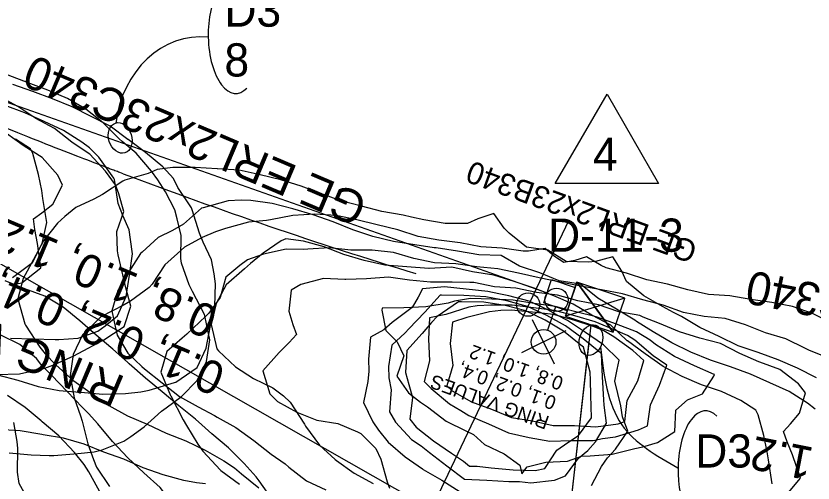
# Model space of a CAD drawing. Extents: x 1638506 to 1658005, y 834807 to 846788.
# Drawn here: x 1640119.8 to 1640408.1, y 842707.5 to 842876.3 of the extents above; entities that cross this region are included whole.
import ezdxf

# ---------------------------------------------------------------- set-up
doc = ezdxf.new("R2010")
doc.units = 0
for name, color, linetype in [('Default', 7, 'Continuous'), ('Old_Level_1', 7, 'Continuous'), ('Old_Level_2', 7, 'Continuous'), ('Scratch_Level_0', 7, 'Continuous')]:
    doc.layers.add(name, color=color, linetype=linetype)

msp = doc.modelspace()

# ---------------------------------------------------------------- linework, layer by layer
at = {"layer": 'Default'}
for p, q in [((1640075.68, 842859.56), (1640311.9, 842776.31)), ((1640114.23, 842786.79), (1640314.63, 842672.83)), ((1640335.82, 842762.04), (1640322.64, 842780.16)), ((1640339.96, 842774.32), (1640318.49, 842767.88)), ((1640314.9, 842771.23), (1640312.04, 842762.75)), ((1640314.6, 842750.52), (1640306.64, 842766.54)), ((1640303.08, 842545.23), (1640327.81, 842764.74)), ((1640318.6, 842762.5), (1640302.6, 842754.57)), ((1640314.65, 842760.54), (1640314.65, 842760.54)), ((1640303.88, 842552.36), (1640327.15, 842758.82)), ((1640310.61, 842758.51), (1640310.61, 842758.51))]:
    msp.add_line(p, q, dxfattribs=at)
for points in [[(1640352.23, 842815.78), (1640314.84, 842815.78), (1640333.66, 842848.05)], [(1640321.99, 842778.25), (1640319.14, 842769.8), (1640310.66, 842772.66), (1640313.51, 842781.11)], [(1640339.96, 842774.32), (1640322.64, 842780.16), (1640318.49, 842767.88), (1640335.82, 842762.04)], [(1640329.23, 842771.1), (1640318.49, 842767.88), (1640322.64, 842780.16)], [(1640329.23, 842771.1), (1640335.82, 842762.04), (1640339.96, 842774.32)]]:
    msp.add_lwpolyline(points, close=True, dxfattribs=at)
msp.add_circle((1640310.61, 842758.55), 4.47, dxfattribs=at)
for centre, major_axis, ratio, start_param, end_param in [((1640198.9, 842868.83), (-0.49, 20.52), 0.466223, 5.884886, 7.853982), ((1640185.55, 842834.26), (-3.78, -34.34), 0.862742, 3.141593, 4.712389), ((1640198.9, 842868.83), (-0.49, 20.52), 0.466223, 1.570796, 3.572354), ((1640368.8, 842713.14), (-0.49, -20.52), 0.466223, 2.710831, 4.712389), ((1640368.8, 842713.14), (-0.49, -20.52), 0.466223, 4.712389, 6.681485)]:
    msp.add_ellipse(centre, major_axis=major_axis, ratio=ratio, start_param=start_param, end_param=end_param, dxfattribs=at)
for centre, major_axis in [((1640157.49, 842832.23), (1.72, -5.4)), ((1640327.74, 842759.18), (1.72, 5.4))]:
    msp.add_ellipse(centre, major_axis=major_axis, ratio=0.730797, dxfattribs=at)
msp.add_spline([(1640331.21, 842756.76), (1640338.9, 842728.6), (1640359.22, 842712.98)], degree=3, dxfattribs=at)
at = {"layer": 'Old_Level_1'}
for points in [[(1640113.03, 842746.65), (1640120.46, 842744.71), (1640127.77, 842742.43), (1640135.38, 842740.98), (1640142.84, 842740.36), (1640143.29, 842740.34), (1640151.19, 842739.68), (1640159.42, 842739.92), (1640164.95, 842740.45), (1640168, 842741.12), (1640177.13, 842743.83), (1640177.61, 842743.99), (1640185.3, 842749.33), (1640188.61, 842756.26), (1640190.07, 842763.87), (1640191.69, 842771.42), (1640191.96, 842779.47), (1640191.42, 842783.1), (1640190.48, 842788.15), (1640187.45, 842794.55), (1640186.15, 842797.87), (1640183.57, 842806.27), (1640183.31, 842807.04), (1640178.34, 842814.27), (1640176.76, 842817.56), (1640172.93, 842821.76), (1640166.66, 842826.92), (1640160.32, 842831.69), (1640160.27, 842831.72), (1640153.85, 842836.44), (1640146.99, 842839.96), (1640140.11, 842843.44), (1640133.04, 842846.37), (1640125.87, 842849.03), (1640118.63, 842851.51)], [(1640117.85, 842759.92), (1640125.88, 842759.6), (1640133.96, 842759.43), (1640135.26, 842759.4), (1640142.27, 842759.89), (1640149.36, 842762.41), (1640152.03, 842764.34), (1640156.55, 842767.93), (1640159.61, 842774.96), (1640160.88, 842782.64), (1640161.88, 842790.41), (1640161.8, 842791.19), (1640160.72, 842798.98), (1640158.4, 842804.22), (1640156.8, 842808.55), (1640155.47, 842817.17), (1640155.16, 842817.67), (1640149.81, 842825.34), (1640146.39, 842828.62), (1640143.62, 842830.7), (1640137.02, 842834.93), (1640130.05, 842838.15), (1640123.05, 842841.29), (1640115.86, 842843.92)], [(1640118.59, 842781.75), (1640125.83, 842787.25), (1640129.31, 842794.13), (1640130.93, 842801.68), (1640129.51, 842810.34), (1640129.12, 842813.24), (1640127.94, 842819.05), (1640125.84, 842826.6), (1640125.02, 842828.25), (1640119.57, 842831.74)], [(1640409.37, 842745.59), (1640402.5, 842749.07), (1640395.43, 842752.01), (1640388.25, 842754.66), (1640381.01, 842757.14), (1640374.11, 842760.54), (1640367.15, 842763.77), (1640360.44, 842767.71), (1640357.63, 842769.15), (1640353.6, 842771.29), (1640346.89, 842775.21), (1640340.61, 842780.32), (1640338.91, 842784.1), (1640335.71, 842789.23), (1640329.43, 842787.55), (1640326.88, 842787.35), (1640318.81, 842787.53), (1640312.2, 842791.73), (1640304.43, 842792.76), (1640298.13, 842797.82), (1640296.31, 842799.61), (1640292.57, 842804.93), (1640286.83, 842803.06), (1640283.1, 842801.26), (1640275, 842801.37), (1640267.34, 842802.69), (1640262.87, 842803.64), (1640259.8, 842804.34), (1640252.13, 842805.63), (1640244.72, 842807.64), (1640237.24, 842809.47), (1640230.1, 842812.22), (1640222.9, 842814.8), (1640215.6, 842817.1), (1640208.09, 842818.85), (1640200.57, 842820.56), (1640192.62, 842821.08), (1640192.56, 842821.09), (1640184.64, 842821.51), (1640176.52, 842821.58), (1640170.89, 842820.83), (1640167.56, 842819.33), (1640159.11, 842816.98), (1640158.41, 842816.56), (1640151.04, 842811.78), (1640147.91, 842810.07), (1640141.47, 842807.12), (1640137.51, 842803.85), (1640134.76, 842801.42), (1640129.79, 842795.09), (1640126.18, 842788.26), (1640122.41, 842781.49), (1640120.48, 842774.05), (1640122.94, 842765.02)], [(1640408.78, 842734.25), (1640406.01, 842736.34), (1640399.4, 842740.57), (1640392.44, 842743.79), (1640385.44, 842746.92), (1640378.25, 842749.55), (1640370.96, 842751.89), (1640363.88, 842754.79), (1640356.99, 842758.23), (1640350.28, 842762.18), (1640344.24, 842765.88), (1640343.66, 842766.35), (1640337, 842770.42), (1640330.27, 842774.3), (1640323.97, 842779.34), (1640316.3, 842780.63), (1640309.21, 842783.53), (1640301.92, 842785.87), (1640295.21, 842789.8), (1640287.14, 842790), (1640279.49, 842791.35), (1640271.77, 842792.51), (1640271.03, 842792.53), (1640264.02, 842793.58), (1640256.35, 842794.86), (1640248.86, 842796.66), (1640241.57, 842798.98), (1640234.48, 842801.88), (1640227.29, 842804.48), (1640219.91, 842806.58), (1640212.5, 842808.6), (1640204.72, 842809.6), (1640201.25, 842809.78), (1640196.53, 842809.47), (1640187.51, 842807.03), (1640186.95, 842806.85), (1640180.38, 842801.1), (1640176.37, 842798.81), (1640171.23, 842796.29), (1640165.4, 842791.02), (1640164.83, 842790.47), (1640160.61, 842783.87), (1640156.64, 842777.17), (1640154.47, 842769.82)], [(1640393.32, 842707.31), (1640391.9, 842715.97), (1640391.51, 842718.87), (1640390.32, 842724.68), (1640388.23, 842732.23), (1640387.41, 842733.89), (1640381.96, 842737.38), (1640374.99, 842740.58), (1640367.75, 842743.07), (1640360.71, 842746.09), (1640353.88, 842749.69), (1640347.39, 842754.24), (1640340.95, 842758.89), (1640340.84, 842758.98), (1640334.88, 842764.58), (1640328.03, 842768.14), (1640321.35, 842772.14), (1640314.3, 842775.15), (1640307.17, 842777.92), (1640299.92, 842780.38), (1640292.59, 842782.61), (1640284.9, 842783.84), (1640277.37, 842785.51), (1640269.2, 842785.05), (1640269.06, 842785.06), (1640261.13, 842785.63), (1640253.24, 842786.32), (1640245.69, 842787.95), (1640238.35, 842790.16), (1640231.21, 842792.91), (1640223.81, 842794.94), (1640217.4, 842795.77), (1640215.7, 842795.02), (1640209.25, 842790.59), (1640204.6, 842786.9), (1640202.44, 842784.93), (1640195.78, 842779.21), (1640192.17, 842772.38), (1640190.42, 842764.88), (1640192.43, 842756.01)], [(1640327.93, 842706.69), (1640331.59, 842713.5), (1640333.7, 842716.62), (1640336.59, 842719.82), (1640341.1, 842726.32), (1640339.11, 842731.48), (1640338.54, 842735.39), (1640336.43, 842744.3), (1640337.2, 842748.6), (1640337.93, 842751.9), (1640332.31, 842757.52), (1640325.75, 842761.88), (1640319.22, 842766.3), (1640315.58, 842768.17), (1640312.41, 842769.96), (1640305.45, 842773.21), (1640298.03, 842775.19), (1640294.46, 842775.86), (1640290.47, 842776.77), (1640282.62, 842777.58), (1640274.8, 842778.45), (1640266.87, 842777.76), (1640265.31, 842774.76), (1640263.14, 842770.98), (1640255.79, 842765.51), (1640252.85, 842762.88), (1640248.01, 842760.2), (1640247.28, 842752.32)], [(1640254.54, 842749.68), (1640254.67, 842745.52), (1640255.45, 842741.21), (1640254.86, 842733.28), (1640257, 842729.55), (1640262.85, 842723.27), (1640266.31, 842720.97), (1640269.3, 842718.62), (1640275.67, 842713.75), (1640282.04, 842708.89), (1640290.05, 842708.52), (1640298.06, 842708.15), (1640301.86, 842708.04), (1640305.99, 842707.57), (1640314.51, 842708.62), (1640318.54, 842710.1), (1640323.18, 842716.56), (1640326.56, 842719.35), (1640329.33, 842722.46), (1640333.4, 842729.12), (1640332.5, 842735.68), (1640332.45, 842737.61), (1640331.89, 842745.95), (1640331.55, 842754.22), (1640331.22, 842754.54), (1640324.93, 842759.61), (1640318.51, 842764.34), (1640311.73, 842768.1), (1640304.75, 842771.28), (1640297.36, 842773.33), (1640289.75, 842774.8), (1640281.8, 842775.31), (1640273.71, 842775.47), (1640273.26, 842775.43), (1640267.68, 842769.32), (1640261.88, 842763.29), (1640260.61, 842761.85), (1640255.71, 842757.4), (1640254.54, 842749.68)], [(1640260.65, 842747.46), (1640261.93, 842743.11), (1640263.17, 842738.4), (1640262.28, 842730.58), (1640264.48, 842727.74), (1640270.83, 842722.81), (1640277.34, 842718.32), (1640281.61, 842715.41), (1640283.76, 842713.61), (1640286.56, 842713.61), (1640291.71, 842713.09), (1640299.58, 842712.35), (1640307.61, 842712.04), (1640311.12, 842712.81), (1640315.46, 842719.37), (1640319.44, 842722.17), (1640323.22, 842724.68), (1640327.95, 842731.11), (1640327.69, 842739.34), (1640327.63, 842744.66), (1640327.43, 842747.58), (1640325.02, 842756.59), (1640324.1, 842757.34), (1640317.79, 842762.37), (1640311.13, 842766.44), (1640304.21, 842769.78), (1640296.75, 842771.67), (1640289.04, 842772.84), (1640280.97, 842773.04), (1640279.79, 842773.06), (1640272.14, 842767.7), (1640270.12, 842765.6), (1640266.65, 842761.56), (1640261.16, 842755.41), (1640260.65, 842747.46)], [(1640154.47, 842769.82), (1640155.62, 842764.16), (1640156.43, 842760.97), (1640160.24, 842754.48), (1640165.29, 842749.6), (1640166.31, 842748.79), (1640172.61, 842743.73), (1640178.96, 842738.81), (1640185.73, 842735.05), (1640191.55, 842731.9), (1640192.53, 842731.35), (1640199.31, 842727.63), (1640205.76, 842722.97), (1640212.1, 842718.03), (1640217.11, 842714.46), (1640218.53, 842713.32), (1640224.85, 842708.32), (1640231.8, 842705.06)], [(1640122.94, 842765.02), (1640123.22, 842764.59), (1640128.46, 842756.64), (1640130.37, 842754.17), (1640134.26, 842750.21), (1640140.41, 842744.74), (1640146.89, 842740.16), (1640147.25, 842739.89), (1640153.36, 842735.57), (1640160.12, 842731.79), (1640167.19, 842728.84), (1640174.13, 842725.54), (1640181.25, 842722.73), (1640188.17, 842719.37), (1640194.94, 842715.61), (1640198.78, 842712.99), (1640201.34, 842710.84), (1640207.64, 842705.78)], [(1640192.43, 842756.01), (1640193.09, 842755.27), (1640199.14, 842749.52), (1640205.74, 842745.28), (1640212.67, 842741.96), (1640216.54, 842739.09), (1640218.94, 842736.81), (1640224.15, 842728.77), (1640224.45, 842728.07), (1640229.56, 842721.28), (1640235.18, 842716.02), (1640235.66, 842715.67), (1640242.12, 842711.05), (1640248.95, 842707.43)], [(1640247.28, 842752.32), (1640247.44, 842748.02), (1640247.05, 842744.27), (1640245.48, 842736.7), (1640248.9, 842729.66), (1640250.88, 842726.59), (1640254.38, 842722.36), (1640260.56, 842716.97), (1640266.78, 842712.66), (1640267.07, 842712.48), (1640273.79, 842708.59), (1640280.4, 842704.37)], [(1640150.91, 842702.81), (1640150.68, 842703.26), (1640146.14, 842711.64), (1640144.46, 842714.27), (1640140.93, 842718.55), (1640135.28, 842724.54), (1640129.23, 842729.66), (1640128.89, 842729.97), (1640123.18, 842734.8), (1640116.77, 842739.16)], [(1640188.39, 842707.26), (1640185.06, 842707.56), (1640180.49, 842708.42), (1640173.04, 842710.55), (1640165.78, 842713.06), (1640158.76, 842716.11), (1640151.52, 842718.68), (1640144.43, 842721.6), (1640136.98, 842723.71), (1640129.61, 842724.97), (1640129.16, 842725.04), (1640121.34, 842726.38), (1640113.12, 842726.85)]]:
    msp.add_lwpolyline(points, dxfattribs=at)
msp.add_circle((1640305.02, 842772.01), 4.21, dxfattribs=at)
at = {"layer": 'Old_Level_2'}
msp.add_line((1640319.78, 842802.51), (1640164.82, 842477.58), dxfattribs=at)
msp.add_arc((1640787.74, 844492.39), 1787.5, 249.39267, 252.97707, dxfattribs=at)
msp.add_open_spline([(1640158.61, 842819.26), (1640157.59, 842819.64), (1640156.58, 842820.02), (1640154.56, 842820.79), (1640153.54, 842821.17), (1640150.51, 842822.33), (1640144.44, 842824.64), (1640130.31, 842830.13), (1640118.24, 842834.94), (1640094.16, 842844.7), (1640078.16, 842851.39), (1640030.3, 842871.79), (1639998.56, 842885.87), (1639966.8, 842899.95)], degree=3, dxfattribs=at)
at = {"layer": 'Scratch_Level_0'}
for points in [[(1640117.31, 842718.45), (1640125.31, 842717.74), (1640131.79, 842717.47), (1640133.54, 842717.55), (1640142.11, 842718.16), (1640148.09, 842718.87), (1640151, 842719.53), (1640158.77, 842722.65), (1640161.33, 842724.3), (1640166.16, 842727.83), (1640172.46, 842733.46), (1640174.06, 842734.71), (1640179.6, 842738.75), (1640185.37, 842744.61), (1640188.71, 842751.5), (1640189.95, 842759.28), (1640188.13, 842767.9), (1640188.03, 842768.41), (1640183.6, 842776.79), (1640182.41, 842779.1), (1640179.62, 842787.02), (1640179.38, 842788.7), (1640179.55, 842796.93), (1640178.08, 842802.96), (1640177.23, 842806.22), (1640173.93, 842812.78), (1640171.16, 842817.11), (1640168.77, 842820.2), (1640163.22, 842826.72), (1640158.23, 842830.9), (1640157.13, 842831.94), (1640151.28, 842837.75), (1640145.06, 842842.67), (1640138.39, 842846.54), (1640131.35, 842849.53), (1640124.15, 842852.15), (1640117.01, 842854.91)], [(1640112.67, 842746.71), (1640121.05, 842746.96), (1640121.09, 842746.96), (1640130.28, 842749.05), (1640133.18, 842750.12), (1640140.43, 842753.38), (1640142.55, 842754.46), (1640151.14, 842759.04), (1640151.22, 842759.09), (1640158.88, 842764.15), (1640161.31, 842771.43), (1640159.42, 842778.57), (1640158.93, 842780.75), (1640156.78, 842789.97), (1640156.57, 842791.43), (1640156.3, 842798.48), (1640158.85, 842805.71), (1640157, 842812.05), (1640155.85, 842815.29), (1640152.17, 842820.26), (1640146.46, 842826.39), (1640141.19, 842829.82), (1640139.99, 842830.72), (1640133.76, 842835.62), (1640126.98, 842839.23), (1640120.51, 842843.56), (1640113.75, 842847.22)], [(1640118.1, 842779.11), (1640121.87, 842779.85), (1640128.73, 842785.25), (1640127.55, 842794.06), (1640126.58, 842799.11), (1640126.09, 842802.98), (1640129.16, 842805.18), (1640133.08, 842808.33), (1640136.65, 842815.13), (1640134.92, 842818.77), (1640129.32, 842825.16), (1640122.75, 842829.26), (1640122.45, 842829.46), (1640116.38, 842833.82)], [(1640415.01, 842765.3), (1640407.92, 842768.85), (1640400.6, 842771.29), (1640393.1, 842772.79), (1640385.52, 842773.89), (1640377.97, 842775.14), (1640370.27, 842775.66), (1640362.81, 842777.37), (1640355.42, 842779.4), (1640347.93, 842780.98), (1640340.61, 842783.42), (1640333.19, 842785.29), (1640331.39, 842786.11), (1640326.17, 842789.24), (1640321.94, 842787.99), (1640317.98, 842787.27), (1640314.61, 842789.45), (1640311.17, 842792.23), (1640305.15, 842791.34), (1640303.18, 842791.27), (1640295.6, 842792.39), (1640287.91, 842792.94), (1640280.39, 842794.36), (1640272.78, 842795.31), (1640265.24, 842796.6), (1640257.93, 842799.07), (1640250.48, 842800.81), (1640243.05, 842802.7), (1640235.55, 842804.19), (1640227.86, 842804.74), (1640219.94, 842804.18), (1640211.84, 842802.66), (1640210.35, 842802.43), (1640203.87, 842801.78), (1640195.61, 842799.52), (1640191.9, 842798.31), (1640187.17, 842796.29), (1640180.75, 842792.73), (1640178.22, 842790.5), (1640173.6, 842786.35), (1640169.11, 842779.45), (1640167.96, 842778.2), (1640161.21, 842773.22), (1640158.92, 842771.98), (1640150.54, 842767.55), (1640150.17, 842767.18), (1640143.82, 842761.09), (1640140.46, 842753.96), (1640139.35, 842746.38), (1640140.81, 842738.28)], [(1640412.6, 842753.2), (1640406.74, 842755.49), (1640405.38, 842756.13), (1640398.28, 842759.66), (1640390.91, 842761.81), (1640383.69, 842764.74), (1640376.34, 842766.96), (1640368.69, 842767.72), (1640361.18, 842769.2), (1640353.9, 842771.78), (1640346.49, 842773.74), (1640339.13, 842775.96), (1640331.6, 842777.34), (1640324.06, 842778.63), (1640316.55, 842780.07), (1640309.06, 842781.63), (1640301.59, 842783.32), (1640294.11, 842784.93), (1640286.47, 842785.7), (1640278.87, 842786.73), (1640271.15, 842787.15), (1640263.65, 842788.65), (1640256.3, 842790.88), (1640248.65, 842791.65), (1640240.86, 842791.72), (1640233.23, 842792.56), (1640225.32, 842792.01), (1640223.82, 842791.94), (1640217.53, 842792.08), (1640209.36, 842790.22), (1640203.53, 842788.19), (1640200.75, 842786.15), (1640195.65, 842781.96), (1640193.7, 842774.55), (1640189.51, 842768.87), (1640188.51, 842767.78), (1640181.54, 842761.37), (1640179.91, 842759.85), (1640174.32, 842755.01), (1640172.24, 842747.62), (1640175.72, 842739.13)], [(1640212.68, 842701.37), (1640207.69, 842708.36), (1640206.63, 842709.76), (1640202.3, 842714.58), (1640196.65, 842720.3), (1640190.62, 842725.28), (1640187.04, 842728.56), (1640184.78, 842730.64), (1640178.64, 842735.43), (1640172.64, 842740.46), (1640166.63, 842745.49), (1640160.69, 842750.65), (1640160.07, 842751.19), (1640154.79, 842755.88), (1640148.81, 842760.97), (1640142.85, 842766.1), (1640136.81, 842771.06), (1640130.25, 842775.02), (1640123, 842777.66), (1640115.89, 842780.57)], [(1640397.96, 842702.63), (1640403.58, 842709.31), (1640400.64, 842717.7), (1640398.67, 842722.45), (1640397.4, 842726.15), (1640399.96, 842728.92), (1640403.15, 842732.8), (1640405.28, 842740.18), (1640402.84, 842743.39), (1640396.06, 842748.52), (1640388.8, 842751.2), (1640388.46, 842751.33), (1640381.63, 842754.37), (1640374.55, 842757.99), (1640367.12, 842759.87), (1640359.77, 842762.13), (1640352.58, 842765.18), (1640346.62, 842767.47), (1640345.36, 842768.08), (1640337.83, 842769.43), (1640330.53, 842771.96), (1640323.02, 842773.41), (1640315.62, 842775.44), (1640308.01, 842776.4), (1640300.52, 842777.94), (1640292.81, 842778.4), (1640285.34, 842780.05), (1640283.93, 842779.96), (1640277.56, 842780.13), (1640269.74, 842780.07), (1640262.09, 842780.8), (1640254.51, 842781.91), (1640246.58, 842781.29), (1640239.11, 842781.1), (1640238.75, 842781.1), (1640231.01, 842781.41), (1640222.78, 842779.28), (1640219.3, 842777.24), (1640218.44, 842769.62), (1640219.9, 842764.81), (1640221.2, 842761.27), (1640218.61, 842758.34), (1640214.97, 842754.71), (1640209.03, 842748.09), (1640211.66, 842739.76)], [(1640252.18, 842770.69), (1640252.14, 842770.03), (1640253.5, 842762.63), (1640257.65, 842758.55), (1640260.11, 842753.51), (1640257.59, 842746.21), (1640261.77, 842740.08), (1640266.07, 842736.72), (1640268.57, 842735.02), (1640275.35, 842729.95), (1640282.44, 842726.38), (1640285.25, 842725.1), (1640289.26, 842721.44), (1640296.4, 842718.12), (1640302.01, 842713.96), (1640302.74, 842710.82), (1640304.62, 842713.44), (1640311.4, 842715.13), (1640319.27, 842715.46), (1640324.37, 842717.3), (1640327.46, 842717.4), (1640335.37, 842717.99), (1640343.59, 842720.07), (1640346.55, 842720.68), (1640351.8, 842722.14), (1640358.02, 842726.2), (1640358.49, 842733.9), (1640362.69, 842737.62), (1640368.08, 842739.79), (1640372.18, 842746.11), (1640372.39, 842746.73), (1640372.32, 842746.78), (1640365.14, 842749.91), (1640358.01, 842753.27), (1640351.07, 842757.6), (1640349.17, 842759.16), (1640344.19, 842762.21), (1640336.94, 842764.97), (1640329.66, 842767.58), (1640322.23, 842769.46), (1640314.8, 842771.32), (1640307.23, 842772.45), (1640299.65, 842773.57), (1640291.92, 842773.94), (1640284.17, 842774.17), (1640278.4, 842773.27), (1640276.05, 842772.55), (1640267.98, 842771.21), (1640260.1, 842770.85), (1640252.28, 842770.71), (1640252.18, 842770.69)], [(1640267.44, 842744.25), (1640269.9, 842741.72), (1640276.6, 842736.19), (1640280.67, 842733.81), (1640283.55, 842731.91), (1640290.74, 842728.88), (1640297.91, 842725.71), (1640305.38, 842724.03), (1640312.92, 842722.72), (1640320.75, 842722.89), (1640328.56, 842722.94), (1640331.94, 842723.59), (1640336.62, 842724.23), (1640344.93, 842726.77), (1640348.17, 842728.16), (1640349.25, 842735.74), (1640352.57, 842742.88), (1640355.24, 842750.15), (1640350.24, 842753.46), (1640343.57, 842759.11), (1640340.95, 842760.8), (1640336.51, 842762.81), (1640329.3, 842765.81), (1640321.92, 842767.9), (1640314.51, 842769.85), (1640306.92, 842770.89), (1640299.29, 842771.79), (1640291.49, 842771.78), (1640286.62, 842771.63), (1640283.55, 842771.07), (1640275.22, 842768.41), (1640269.34, 842767.27), (1640269.02, 842759.53), (1640269.35, 842751.67), (1640267.44, 842744.25)], [(1640275.63, 842742.62), (1640277.53, 842740.87), (1640284.53, 842736.85), (1640291.82, 842734.26), (1640299.02, 842731.28), (1640306.56, 842729.97), (1640314.03, 842728.29), (1640321.82, 842728.28), (1640329.54, 842727.88), (1640337.55, 842728.91), (1640339.97, 842729.79), (1640340.81, 842737.42), (1640344.72, 842744.45), (1640346.88, 842751.82), (1640342.83, 842755.41), (1640336.03, 842760.41), (1640332.37, 842762.51), (1640328.95, 842764.03), (1640321.61, 842766.35), (1640314.22, 842768.38), (1640306.61, 842769.34), (1640298.94, 842770.02), (1640295.2, 842769.92), (1640291.01, 842769.38), (1640282.81, 842767.37), (1640277.7, 842765.61), (1640276.87, 842757.97), (1640277.78, 842749.99), (1640275.63, 842742.62)], [(1640186.93, 842668.27), (1640186.91, 842668.37), (1640184.98, 842677.91), (1640184.46, 842680.23), (1640182.35, 842687.89), (1640181.33, 842690.81), (1640177.08, 842699.23), (1640177.06, 842699.26), (1640171.92, 842705.88), (1640166.08, 842711.23), (1640160.28, 842716.6), (1640160.26, 842716.62), (1640154.71, 842722.53), (1640149.4, 842728.92), (1640145.99, 842732.64), (1640143.88, 842734.89), (1640138.25, 842740.64), (1640132.68, 842746.51), (1640129.19, 842749.98), (1640127.18, 842752.52), (1640121.22, 842757.64), (1640114.3, 842760.92)], [(1640140.81, 842738.28), (1640143.12, 842731.83), (1640143.74, 842729.9), (1640145.78, 842721.69), (1640147.78, 842716.06), (1640148.97, 842713.26), (1640153.64, 842706.31)], [(1640175.72, 842739.13), (1640175.76, 842739.04), (1640180.28, 842730.42), (1640181.43, 842728.33), (1640185.58, 842721.56), (1640187.38, 842719.05), (1640193.8, 842712.14), (1640193.83, 842712.12), (1640200.62, 842707.19)], [(1640211.66, 842739.76), (1640214.36, 842737.04), (1640221.38, 842733.12), (1640228.62, 842730.29), (1640236.16, 842729.01), (1640243.37, 842726.03), (1640244.49, 842725.42), (1640249.97, 842720), (1640251.71, 842716.18), (1640254, 842707.92), (1640254.91, 842705.63)], [(1640152.23, 842677.67), (1640150.4, 842681.05), (1640144.75, 842686.76), (1640138.59, 842691.5), (1640131.7, 842694.83), (1640125.6, 842699.69), (1640124.7, 842700.6), (1640120.95, 842707.33), (1640120.34, 842711.48), (1640120.44, 842720.05), (1640120.21, 842722.51), (1640119, 842729.42)]]:
    msp.add_lwpolyline(points, dxfattribs=at)
msp.add_circle((1640315.28, 842773.72), 4.21, dxfattribs=at)

# ---------------------------------------------------------------- texts
at = {"layer": 'Default'}
for s, height, p in [('D3', 11.995, (1640195.19, 842872.43)), ('8', 12, (1640195.19, 842854.43)), ('4', 12, (1640328.49, 842820.39)), ('D-11-3', 12, (1640312.26, 842791.11)), ('D3', 12, (1640365.47, 842713.13))]:
    msp.add_text(s, height=height, dxfattribs=at).set_placement(p)
at = {"layer": 'Old_Level_1'}
for s, height, p in [('GE ERL2x23B340', 8, (1640366.76, 842794.26)), ('0.8, 1.0, 1.2', 5, (1640318.19, 842745.56)), ('0.1, 0.2, 0.4,', 5, (1640315.62, 842738.51)), ('RING VALUES', 5, (1640313.06, 842731.47))]:
    msp.add_text(s, height=height, rotation=160, dxfattribs=at).set_placement(p)
at = {"layer": 'Scratch_Level_0'}
for s, rotation, p in [('GE ERL2x23C340', 157.0176, (1640247.64, 842810.99)), ('0.8, 1.0, 1.2', 157.0176, (1640193.55, 842770.47)), ('RING VALUES', 157.0176, (1640159.79, 842745.68)), ('0.1, 0.2, 0.4,', 157.0176, (1640196.25, 842749.77)), ('GE ERL2x23C340', 168.7284, (1640514.8, 842758.65)), ('0.8, 1.0, 1.2', 168.7284, (1640470.05, 842708))]:
    msp.add_text(s, height=12, rotation=rotation, dxfattribs=at).set_placement(p)

doc.saveas('drawing.dxf')
